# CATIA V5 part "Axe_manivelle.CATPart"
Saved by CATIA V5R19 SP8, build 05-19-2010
Part number: Axe manivelle
Bounding box of the stored display mesh (mm): x -11 to 11, y -1.919 to 1.919, z -1.919 to 1.919
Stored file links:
  C:\Users\ThinkMotion\Desktop\EU_thinkMotion\iao\IAO_MMS_Groupe3\ecartoux\projet_IAO_ecartoux\projet_IAO_ecartoux\griffe_d'une_camera_ecartoux\Axe_manivelle.CATPart
  C:\Users\ThinkMotion\Desktop\EU_thinkMotion\iao\IAO_MMS_Groupe3\ecartoux\projet_IAO_ecartoux\projet_IAO_ecartoux\griffe_d'une_camera_ecartoux\Mecanisme_a_coulisse_et_leviers_de_la_griffe_d'un_camera_ecartoux.CATProduct
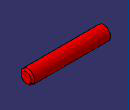
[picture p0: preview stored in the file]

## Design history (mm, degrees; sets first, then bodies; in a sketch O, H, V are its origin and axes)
Set1
  Plane1 "Plan.2": linked copy from another document
  Line1: linked copy from another document
  Point1: linked copy from another document
Body1 (main body)
  Sketch1 on Plane1, origin (0, 0, 0), H (1, 0, 0), V (0, 1, 0)
    line L1 (-11, 2) -> (11, 2)
    line L2 (11, 2) -> (11, 0)
    line L3 (11, 0) -> (-11, 0)
    line L4 (-11, 0) -> (-11, 2)
    reference projected line E1 (11, 0) -> (-10.5, 0) from Line1
    reference projected point E2 (0, 0) from Point1
    distance L2 L4 = 22
    distance L1 L3 = 2
    distance L2 E2 = 11
    horizontal: L1 H, L3 H
    vertical: L2 V, L4 V
    coincidence: E1 L3
  Shaft1: profile Sketch1, axis Line1, angle 360
  Chamfer1: length 0.5, angle 45, on edge [face of Shaft1 from Sketch1.L2 | face of Shaft1 from Sketch1.L1]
